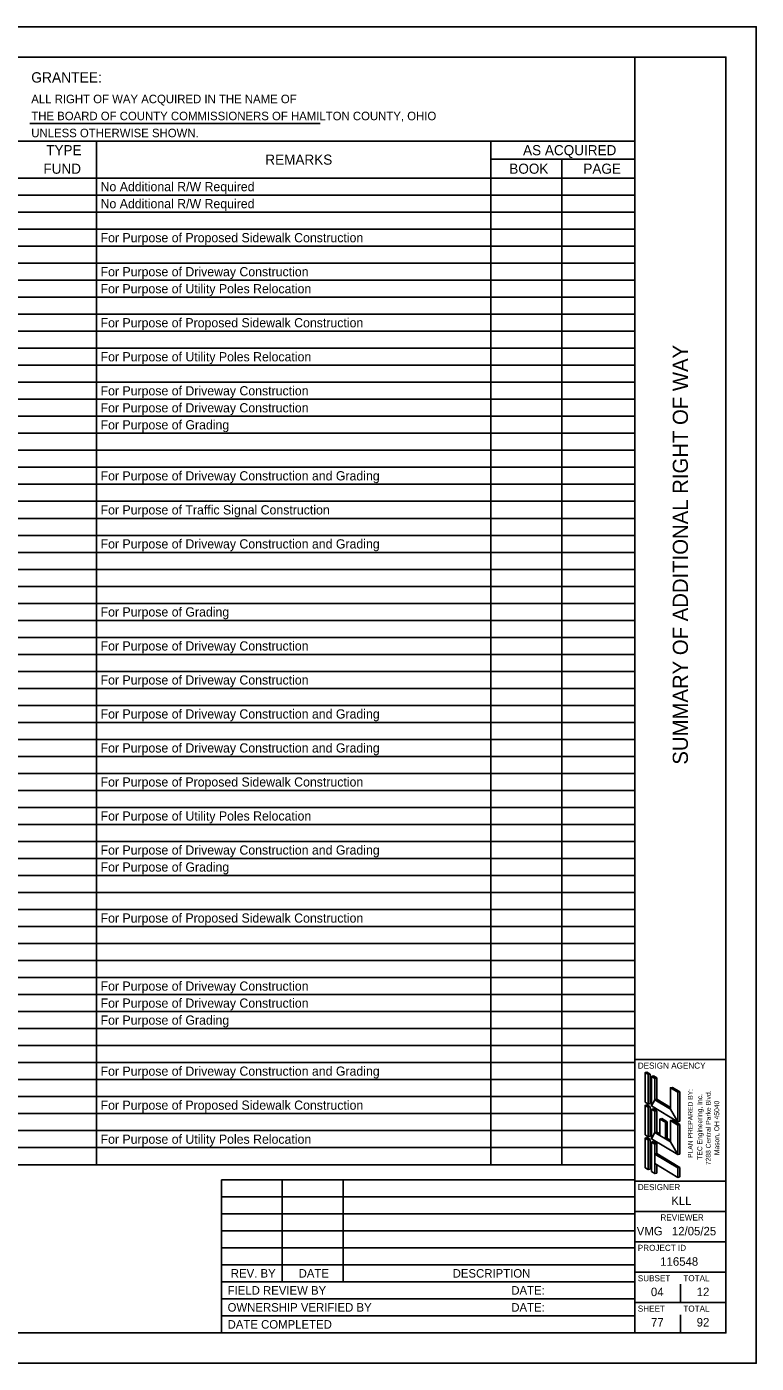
# Model space of a CAD drawing. Extents: x 0 to 34, y 0 to 22.
# Drawn here: x 21.99 to 34, y 0 to 22 of the extents above; entities that cross this region are included whole.
import ezdxf

# ---------------------------------------------------------------- set-up
doc = ezdxf.new("R2010")
doc.units = 0
for name, color, linetype in [('Default', 7, 'Continuous'), ('SH_Border', 7, 'Continuous'), ('SH_Cut_Line', 7, 'Continuous'), ('SH_Data', 7, 'Continuous'), ('SH_Text', 7, 'Continuous')]:
    doc.layers.add(name, color=color, linetype=linetype)

msp = doc.modelspace()

# ---------------------------------------------------------------- linework, layer by layer
at = {"layer": 'Default'}
for p, q in [((1.5, 21.5), (32, 21.5)), ((32, 0.502), (32, 21.5)), ((1.5, 20.117), (32, 20.117)), ((23.14, 20.117), (23.14, 3.269)), ((29.629, 20.117), (29.629, 3.269)), ((32, 20.117), (32, 3.269)), ((29.629, 19.82), (32, 19.82)), ((30.798, 19.82), (30.798, 3.269)), ((1.5, 19.507), (32, 19.507)), ((1.5, 19.227), (32, 19.227)), ((1.5, 18.947), (32, 18.947)), ((1.5, 18.667), (32, 18.667)), ((1.5, 18.387), (32, 18.387)), ((1.5, 18.107), (32, 18.107)), ((1.5, 17.827), (32, 17.827)), ((1.5, 17.548), (32, 17.548)), ((1.5, 17.268), (32, 17.268)), ((1.5, 16.988), (32, 16.988)), ((1.5, 16.708), (32, 16.708)), ((1.5, 16.428), (32, 16.428)), ((1.5, 16.148), (32, 16.148)), ((1.5, 15.868), (32, 15.868)), ((1.5, 15.588), (32, 15.588)), ((1.5, 15.308), (32, 15.308)), ((1.5, 15.028), (32, 15.028)), ((1.5, 14.748), (32, 14.748)), ((1.5, 14.468), (32, 14.468)), ((1.5, 14.188), (32, 14.188)), ((1.5, 13.908), (32, 13.908)), ((1.5, 13.628), (32, 13.628)), ((1.5, 13.348), (32, 13.348)), ((1.5, 13.068), (32, 13.068)), ((1.5, 12.788), (32, 12.788)), ((1.5, 12.508), (32, 12.508)), ((1.5, 12.228), (32, 12.228)), ((1.5, 11.948), (32, 11.948)), ((1.5, 11.668), (32, 11.668)), ((1.5, 11.388), (32, 11.388)), ((1.5, 11.108), (32, 11.108)), ((1.5, 10.828), (32, 10.828)), ((1.5, 10.548), (32, 10.548)), ((1.5, 10.268), (32, 10.268)), ((1.5, 9.988), (32, 9.988)), ((1.5, 9.708), (32, 9.708)), ((1.5, 9.428), (32, 9.428)), ((1.5, 9.148), (32, 9.148)), ((1.5, 8.869), (32, 8.869)), ((1.5, 8.589), (32, 8.589)), ((1.5, 8.309), (32, 8.309)), ((1.5, 8.029), (32, 8.029)), ((1.5, 7.749), (32, 7.749)), ((1.5, 7.469), (32, 7.469)), ((1.5, 7.189), (32, 7.189)), ((1.5, 6.909), (32, 6.909)), ((1.5, 6.629), (32, 6.629)), ((1.5, 6.349), (32, 6.349)), ((1.5, 6.069), (32, 6.069)), ((1.5, 5.789), (32, 5.789)), ((1.5, 5.509), (32, 5.509)), ((1.5, 5.229), (32, 5.229)), ((1.5, 4.949), (32, 4.949)), ((1.5, 4.669), (32, 4.669)), ((1.5, 4.389), (32, 4.389)), ((1.5, 4.109), (32, 4.109)), ((1.5, 3.829), (32, 3.829)), ((1.5, 3.549), (32, 3.549)), ((1.5, 3.269), (32, 3.269)), ((1.5, 0.502), (32, 0.502))]:
    msp.add_line(p, q, dxfattribs=at)
at = {"layer": 'SH_Border'}
for p, q in [((32, 0.5), (32, 21.5)), ((32, 5), (33.5, 5)), ((32, 3), (33.5, 3)), ((32, 2.5), (33.5, 2.5)), ((32, 2), (33.5, 2)), ((32, 1.5), (33.5, 1.5)), ((32, 1), (33.5, 1))]:
    msp.add_line(p, q, dxfattribs=at)
msp.add_lwpolyline([(1.5, 21.5), (33.5, 21.5), (33.5, 0.5), (1.5, 0.5)], close=True, dxfattribs=at)
at = {"layer": 'SH_Cut_Line'}
msp.add_lwpolyline([(0, 0), (34, 0), (34, 22), (0, 22)], close=True, dxfattribs=at)
at = {"layer": 'SH_Data'}
for p, q in [((32.75, 4), (32.75, 4)), ((32.75, 1), (32.75, 1.3)), ((32.375, 0.675), (32.375, 0.675)), ((32.75, 0.5), (32.75, 0.8))]:
    msp.add_line(p, q, dxfattribs=at)
at = {"layer": 'SH_Text'}
for p, q in [((22.043, 20.405), (26.823, 20.405)), ((32.169, 4.785), (32.201, 4.794)), ((32.169, 4.299), (32.169, 4.785)), ((32.223, 4.753), (32.169, 4.785)), ((32.255, 4.761), (32.201, 4.794)), ((32.223, 4.753), (32.255, 4.761)), ((32.223, 4.267), (32.223, 4.753)), ((32.255, 4.275), (32.255, 4.761)), ((32.277, 4.721), (32.309, 4.729)), ((32.331, 4.688), (32.277, 4.721)), ((32.277, 4.235), (32.277, 4.721)), ((32.309, 4.729), (32.363, 4.696)), ((32.331, 4.688), (32.363, 4.696)), ((32.331, 4.337), (32.331, 4.688)), ((32.363, 4.696), (32.363, 4.345)), ((32.587, 4.534), (32.62, 4.542)), ((32.587, 4.183), (32.587, 4.534)), ((32.709, 4.461), (32.587, 4.534)), ((32.62, 4.542), (32.741, 4.47)), ((32.709, 4.461), (32.741, 4.47)), ((32.709, 3.975), (32.709, 4.461)), ((32.741, 4.47), (32.741, 3.984)), ((32.223, 4.267), (32.169, 4.299)), ((32.169, 4.245), (32.201, 4.254)), ((32.169, 3.759), (32.169, 4.245)), ((32.223, 4.213), (32.169, 4.245)), ((32.255, 4.222), (32.201, 4.254)), ((32.223, 4.267), (32.255, 4.275)), ((32.223, 4.213), (32.255, 4.222)), ((32.223, 3.727), (32.223, 4.213)), ((32.255, 3.736), (32.255, 4.222)), ((32.709, 3.975), (32.277, 4.235)), ((32.277, 4.181), (32.309, 4.189)), ((32.277, 3.695), (32.277, 4.181)), ((32.331, 4.148), (32.277, 4.181)), ((32.309, 4.189), (32.363, 4.156)), ((32.331, 4.337), (32.363, 4.345)), ((32.587, 4.183), (32.331, 4.337)), ((32.363, 4.345), (32.587, 4.211)), ((32.331, 4.148), (32.363, 4.156)), ((32.331, 3.797), (32.331, 4.148)), ((32.363, 4.156), (32.363, 3.805)), ((32.415, 4.019), (32.448, 4.027)), ((32.415, 4.019), (32.415, 3.747)), ((32.415, 4.019), (32.503, 3.966)), ((32.448, 4.027), (32.535, 3.974)), ((32.503, 3.966), (32.535, 3.974)), ((32.503, 3.966), (32.503, 3.694)), ((32.535, 3.974), (32.535, 3.702)), ((32.587, 3.994), (32.62, 4.002)), ((32.587, 3.643), (32.587, 3.994)), ((32.709, 3.921), (32.587, 3.994)), ((32.62, 4.002), (32.741, 3.93)), ((32.709, 3.975), (32.741, 3.984)), ((32.223, 3.727), (32.169, 3.759)), ((32.331, 3.797), (32.363, 3.805)), ((32.415, 3.747), (32.331, 3.797)), ((32.363, 3.805), (32.415, 3.774)), ((32.709, 3.921), (32.741, 3.93)), ((32.709, 3.435), (32.709, 3.921)), ((32.741, 3.93), (32.741, 3.444)), ((32.169, 3.705), (32.201, 3.715)), ((32.169, 3.219), (32.169, 3.705)), ((32.223, 3.673), (32.169, 3.705)), ((32.255, 3.681), (32.201, 3.715)), ((32.222, 3.673), (32.255, 3.681)), ((32.223, 3.727), (32.255, 3.736)), ((32.223, 3.187), (32.223, 3.673)), ((32.255, 3.195), (32.255, 3.681)), ((32.709, 3.435), (32.277, 3.695)), ((32.277, 3.641), (32.309, 3.651)), ((32.331, 3.608), (32.277, 3.641)), ((32.277, 3.155), (32.277, 3.641)), ((32.309, 3.651), (32.363, 3.616)), ((32.331, 3.608), (32.363, 3.616)), ((32.331, 3.444), (32.331, 3.608)), ((32.363, 3.616), (32.363, 3.452)), ((32.503, 3.694), (32.535, 3.702)), ((32.587, 3.643), (32.503, 3.694)), ((32.535, 3.702), (32.587, 3.671)), ((32.331, 3.444), (32.363, 3.452)), ((32.331, 3.444), (32.709, 3.217)), ((32.363, 3.452), (32.741, 3.225)), ((32.709, 3.435), (32.741, 3.444)), ((32.223, 3.187), (32.169, 3.219)), ((32.223, 3.187), (32.255, 3.195)), ((32.331, 3.122), (32.277, 3.155)), ((32.331, 3.287), (32.709, 3.06)), ((32.331, 3.122), (32.331, 3.287)), ((32.331, 3.122), (32.363, 3.13)), ((32.363, 3.13), (32.363, 3.267)), ((32.709, 3.217), (32.741, 3.225)), ((32.709, 3.06), (32.709, 3.217)), ((32.741, 3.225), (32.741, 3.068)), ((25.197, 3.02), (25.197, 0.5)), ((25.197, 3.02), (32, 3.02)), ((26.197, 3.02), (26.197, 1.34)), ((27.197, 3.02), (27.197, 1.34)), ((32.709, 3.06), (32.741, 3.068)), ((25.197, 2.74), (32, 2.74)), ((25.197, 2.46), (32, 2.46)), ((25.197, 2.18), (32, 2.18)), ((25.197, 1.9), (32, 1.9)), ((25.197, 1.62), (32, 1.62)), ((25.197, 1.34), (32, 1.34)), ((25.197, 1.06), (32, 1.06)), ((25.197, 0.78), (32, 0.78)), ((32, 0.5), (32, 0.5))]:
    msp.add_line(p, q, dxfattribs=at)
for points in [[(32.169, 4.299), (32.223, 4.267), (32.223, 4.753), (32.169, 4.785)], [(32.277, 4.235), (32.331, 4.337), (32.331, 4.688), (32.277, 4.721)], [(32.709, 3.975), (32.587, 4.183), (32.587, 4.534), (32.709, 4.461)], [(32.169, 3.759), (32.223, 3.727), (32.223, 4.213), (32.169, 4.245)], [(32.277, 4.235), (32.331, 4.337), (32.587, 4.183), (32.709, 3.975)], [(32.277, 3.695), (32.331, 3.797), (32.331, 4.148), (32.277, 4.181)], [(32.415, 3.747), (32.415, 4.019), (32.503, 3.966), (32.503, 3.694)], [(32.709, 3.435), (32.587, 3.643), (32.587, 3.994), (32.709, 3.921)], [(32.277, 3.695), (32.331, 3.797), (32.587, 3.643), (32.709, 3.435)], [(32.169, 3.219), (32.223, 3.187), (32.223, 3.673), (32.169, 3.705)], [(32.277, 3.155), (32.331, 3.122), (32.331, 3.608), (32.277, 3.641)], [(32.331, 3.287), (32.331, 3.444), (32.709, 3.217), (32.709, 3.06)]]:
    msp.add_lwpolyline(points, close=True, dxfattribs=at)

# ---------------------------------------------------------------- texts
at = {"layer": 'Default'}
for s, height, p in [('TYPE', 0.1667, (22.311, 19.885)), ('AS ACQUIRED', 0.16666, (30.161, 19.885)), ('REMARKS', 0.1667, (25.918, 19.729)), ('FUND', 0.1667, (22.265, 19.58)), ('BOOK', 0.1667, (29.934, 19.58)), ('PAGE', 0.1667, (31.153, 19.58)), ('No Additional R/W Required', 0.15151, (23.206, 19.292)), ('No Additional R/W Required', 0.15151, (23.206, 19.012)), ('For Purpose of Proposed Sidewalk Construction', 0.15151, (23.206, 18.452)), ('For Purpose of Driveway Construction', 0.15151, (23.206, 17.892)), ('For Purpose of Utility Poles Relocation', 0.15151, (23.206, 17.612)), ('For Purpose of Proposed Sidewalk Construction', 0.15151, (23.206, 17.052)), ('For Purpose of Utility Poles Relocation', 0.15151, (23.206, 16.492)), ('For Purpose of Driveway Construction', 0.15151, (23.206, 15.932)), ('For Purpose of Driveway Construction', 0.15151, (23.206, 15.652)), ('For Purpose of Grading', 0.15151, (23.206, 15.372)), ('For Purpose of Driveway Construction and Grading', 0.15151, (23.206, 14.532)), ('For Purpose of Traffic Signal Construction', 0.15151, (23.206, 13.972)), ('For Purpose of Driveway Construction and Grading', 0.15151, (23.206, 13.412)), ('For Purpose of Grading', 0.15151, (23.206, 12.292)), ('For Purpose of Driveway Construction', 0.15151, (23.206, 11.732)), ('For Purpose of Driveway Construction', 0.15151, (23.206, 11.172)), ('For Purpose of Driveway Construction and Grading', 0.15151, (23.206, 10.613)), ('For Purpose of Driveway Construction and Grading', 0.15151, (23.206, 10.053)), ('For Purpose of Proposed Sidewalk Construction', 0.15151, (23.206, 9.493)), ('For Purpose of Utility Poles Relocation', 0.15151, (23.206, 8.933)), ('For Purpose of Driveway Construction and Grading', 0.15151, (23.206, 8.373)), ('For Purpose of Grading', 0.15151, (23.206, 8.093)), ('For Purpose of Proposed Sidewalk Construction', 0.15151, (23.206, 7.253)), ('For Purpose of Driveway Construction', 0.15151, (23.206, 6.133)), ('For Purpose of Driveway Construction', 0.15151, (23.206, 5.853)), ('For Purpose of Grading', 0.15151, (23.206, 5.573)), ('For Purpose of Driveway Construction and Grading', 0.15151, (23.206, 4.733)), ('For Purpose of Proposed Sidewalk Construction', 0.15151, (23.206, 4.173)), ('For Purpose of Utility Poles Relocation', 0.15151, (23.206, 3.613))]:
    msp.add_text(s, height=height, dxfattribs=at).set_placement(p)
for s, p in [('PLAN PREPARED BY:', (32.954, 3.38)), ('7288 Central Parke Blvd.', (33.25, 3.262)), ('TEC Engineering, Inc.', (33.11, 3.351)), ('Mason, OH 45040', (33.39, 3.425))]:
    msp.add_text(s, height=0.08, rotation=90, dxfattribs=at).set_placement(p)
at = {"layer": 'SH_Data'}
msp.add_text('SUMMARY OF ADDITIONAL RIGHT OF WAY', height=0.25, rotation=90, dxfattribs=at).set_placement((32.875, 9.854))
for s, height, p in [('DESIGN AGENCY', 0.1, (32.05, 4.85)), ('DESIGNER', 0.1, (32.05, 2.85)), ('KLL', 0.14, (32.601, 2.605)), ('REVIEWER', 0.1, (32.422, 2.35)), ('VMG', 0.14, (32.032, 2.105)), ('12/05/25', 0.14, (32.611, 2.105)), ('PROJECT ID', 0.1, (32.05, 1.85)), ('SUBSET', 0.1, (32.05, 1.35)), ('TOTAL', 0.1, (32.8, 1.35)), ('04', 0.14, (32.266, 1.105)), ('12', 0.14, (33.019, 1.105)), ('SHEET', 0.1, (32.05, 0.85)), ('TOTAL', 0.1, (32.8, 0.85)), ('77', 0.14, (32.268, 0.605)), ('92', 0.14, (33.019, 0.605))]:
    msp.add_text(s, height=height, dxfattribs=at).set_placement(p)
at = {"layer": 'SH_Text'}
for s, height, p in [('GRANTEE:', 0.17, (22.065, 21.081)), ('ALL RIGHT OF WAY ACQUIRED IN THE NAME OF', 0.14, (22.065, 20.741)), ('THE BOARD OF COUNTY COMMISSIONERS OF HAMILTON COUNTY, OHIO', 0.14, (22.065, 20.461)), ('UNLESS OTHERWISE SHOWN.', 0.14, (22.065, 20.181)), ('REV. BY', 0.14, (25.35, 1.41)), ('DATE', 0.14, (26.466, 1.41)), ('DESCRIPTION', 0.14, (29.002, 1.41)), ('116548', 0.14, (32.419, 1.605)), ('FIELD REVIEW BY', 0.14, (25.297, 1.13)), ('DATE:', 0.14, (29.967, 1.13)), ('OWNERSHIP VERIFIED BY', 0.14, (25.297, 0.85)), ('DATE:', 0.14, (29.967, 0.85)), ('DATE COMPLETED', 0.14, (25.297, 0.57))]:
    msp.add_text(s, height=height, dxfattribs=at).set_placement(p)

doc.saveas('drawing.dxf')
